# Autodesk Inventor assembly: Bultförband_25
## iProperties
Created: 2007-05
Part Number: Bultförband_25
Document SubType Name: Assembly
Designer: kurs1
Manufacturer: Standard
Standards Organization: Custom
Author: kurs1
